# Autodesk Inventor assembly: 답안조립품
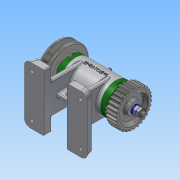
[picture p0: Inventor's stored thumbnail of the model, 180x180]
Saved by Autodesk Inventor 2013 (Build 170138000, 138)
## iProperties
Created: 2016-07
Part Number: 답안조립품
Document SubType Name: Assembly
Designer: Administrator
Author: Administrator
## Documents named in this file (16)
- C:\Users\Administrator\Desktop\460708V1015\답안조립품.iam
- C:\Users\Administrator\Desktop\460708V1015\본체.ipt
- C:\Users\Administrator\Desktop\460708V1015\V벨트풀리.ipt
- C:\Users\Administrator\Desktop\460708V1015\너트 M 8.ipt
- C:\Users\Administrator\Desktop\460708V1015\니플 M 6 x 0.75.ipt
- C:\Users\Administrator\Desktop\460708V1015\베어링 15 x 32 x 9.ipt
- C:\Users\Administrator\Desktop\460708V1015\볼트 M 6 x 8.ipt
- C:\Users\Administrator\Desktop\460708V1015\볼트 M4 x 12.ipt
- C:\Users\Administrator\Desktop\460708V1015\스퍼기어.ipt
- C:\Users\Administrator\Desktop\460708V1015\스프링와셔 8.ipt
- C:\Users\Administrator\Desktop\460708V1015\오일 실 15 25 7.ipt
- C:\Users\Administrator\Desktop\460708V1015\와셔 6x11.5.ipt
- C:\Users\Administrator\Desktop\460708V1015\와셔 8x17.ipt
- C:\Users\Administrator\Desktop\460708V1015\축.ipt
- C:\Users\Administrator\Desktop\460708V1015\커버.ipt
- C:\Users\Administrator\Desktop\460708V1015\키 3 x 3 x 12.ipt
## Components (11 placed, 3 different names)
1. V벨트풀리:1
2. KS B 2023 6002 - 15 x 32 x 9:1
3. KS B 2023 6002 - 15 x 32 x 9:2
4. ISO 4762 M4 x 12:2
5. ISO 4762 M4 x 12:3
6. ISO 4762 M4 x 12:4
7. ISO 4762 M4 x 12:5
8. ISO 4762 M4 x 12:1
9. ISO 4762 M4 x 12:6
10. ISO 4762 M4 x 12:7
11. ISO 4762 M4 x 12:8
